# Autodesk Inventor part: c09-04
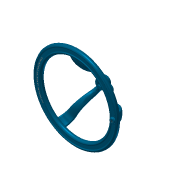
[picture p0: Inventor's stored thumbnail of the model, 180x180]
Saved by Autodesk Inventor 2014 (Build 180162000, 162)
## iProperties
Created: 2010-12
Part Number: c09-04
Document SubType Name: Modeling
Designer: Thom Tremblay
Density: 1 g/cm^3
Material: Generic
Appearance: Sky Blue Dark
Author: Thom Tremblay
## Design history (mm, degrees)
sketch "Sketch2"
  geometry: L1 (0, 0)-(-11.43, 0); L2 (-11.43, 0)-(-11.43, 16.51); L3 (-11.43, 16.51)-(0, 16.51); L4 (0, 16.51)-(0, 0); L5 (-96.52, 66.04)-(-86.36, 66.04); L6 (-86.36, 76.2)-(-96.52, 76.2); L7 (-95.25, 74.93)-(-87.63, 74.93); L8 (-96.52, 76.2)-(-95.25, 74.93); L9 (-86.36, 76.2)-(-87.63, 74.93); A1 r 5.08 centre (-86.36, 71.12) between (-86.36, 66.04) and (-86.36, 76.2); A2 r 5.08 centre (-96.52, 71.12) between (-96.52, 76.2) and (-96.52, 66.04)
  constraints: 18 end point, 4 parallel, 4 point on circle, 4 tangent, 2 centre point, 2 horizontal, 2 perpendicular
  dimensions: "d6" = 16.51 distance of L1.end L2.end; "d7" = 22.86 diameter of L2 L4; "d10" = 5.08 radius of A1; "d11" = 20.32 dimension on A2 A1; "d12" = 3.81 distance from line of A1.centre L7; "d13" = 7.62 distance of L7.start L7.end; "d14" = 76.2 distance from line of L6.end L1; "d15" = 203.2 dimension on A2 L4
revolve "Revolution1" sketch "Sketch2" stored, may be unused: angle "d16" = 120 deg
sketch "Sketch3"
  geometry: L1 (-91.007, -8.89)-(-91.007, 8.89); A1 r 88.9 centre (0, 0) between (-88.479, 8.643) and (-88.479, -8.643); A2 r 93.98 centre (0, 0) between (-93.535, 9.137) and (-93.535, -9.137); A3 r 2.54 centre (-91.007, -8.89) between (-88.479, -8.643) and (-93.535, -9.137); A4 r 2.54 centre (-91.007, 8.89) between (-88.479, 8.643) and (-93.535, 9.137); 2 further points
  constraints: 8 point on circle, 4 centre point, 4 tangent, 2 end point, 1 coincident, 1 midpoint, 1 vertical
  dimensions: "d17" = 17.78 distance of L1.start L1.end; "d18" = 88.9 radius of A1; "d19" = 5.08 diameter of A4
workplane "Work Plane1"
sketch "Sketch4"
  geometry: C1 r 5.08 at (0, 0.635); 1 further point
  constraints: 1 centre point
  dimensions: "d20" = 10.16 diameter of C1; "d21" = 8.89 distance of C1.centre point (0, -8.255)
sketch "3D Sketch1"
sketch "Sketch5"
  geometry: L1 (-91.007, 66.04)-(-91.007, 79.034); L2 (-11.43, 8.89)-(3.26, 8.89); A1 r 19.955 centre (-11.43, 28.845) between (-29.248, 19.86) and (-11.43, 8.89); A2 r 45.954 centre (-70.28, -0.83) between (-29.248, 19.86) and (-70.149, 45.123); A3 r 20.917 centre (-70.09, 66.04) between (-91.007, 66.04) and (-70.149, 45.123); 1 further point
  constraints: 6 point on circle, 4 end point, 4 tangent, 3 centre point, 1 perpendicular, 1 vertical
loft "Loft1" sketch "3D Sketch1", "Sketch5" dims "d22" = 0, "d23" = 90 deg, "d24" = 0, "d25" = 90 deg, "d26" = 0, "d27" = 90 deg
fillet "Fillet1" dims "d28" = 2.54
pattern_circular "Circular Pattern1" dims "d30" = 360 deg
sketch "Sketch6"
  geometry: L1 (-5.08, 3.556)-(5.08, 3.556); L2 (5.08, 3.556)-(5.08, -3.556); L3 (5.08, -3.556)-(-5.08, -3.556); L4 (-5.08, -3.556)-(-5.08, 3.556); 3 further points
  constraints: 8 end point, 2 midpoint, 2 parallel, 1 horizontal, 1 horizontal alignment, 1 perpendicular, 1 vertical alignment
  dimensions: "d32" = 7.112 distance of L3.end L1.start; "d33" = 10.16 distance of L1.start L1.end
extrude "Extrusion2" cut sketch "Sketch6" stored distance "d34" = 25.4; taper "d35" = 0 deg
fillet "Fillet2" dims "d36" = 1.27
sketch "Sketch7"
  geometry: C1 r 6.35 at (91.44, 0); 1 further point
  constraints: 1 centre point
  dimensions: "d37" = 12.7 diameter of C1; "d38" = 91.44 distance of point (0, 0) C1.centre
extrude "Extrusion3" join sketch "Sketch7" distance "d39" = 3.81; taper "d40" = -2 deg
fillet "Fillet3" dims "d41" = 1.27
hole "Hole1" diameter "d44" = 4.9784; stored, may be unused: countersink angle "d48" = 82 deg, drill point angle "d50" = 118 deg; dims "d42" = 25.4, "d43" = 25.4, "d45" = 10.16, "d46" = 9.525, "d47" = 6.35, "d49" = 12.7
sketch "Sketch8"
  geometry: L1 (0, 0)-(-77.65, -44.831); L2 (0, 0)-(-89.662, 0); L3 (0, 0)-(-77.65, 44.831); A1 r 89.662 centre (0, 0) between (-77.65, 44.831) and (-76.203, -47.249); 1 further point
  constraints: 6 end point, 4 point on circle, 1 centre point, 1 coincident, 1 horizontal, 1 other
  dimensions: "d51" = 89.662 radius of A1; "d52" = 30 deg angle of L2 L3 (= 0.5 x d53); "d53" = 60 deg angle of L1 L3
emboss "Emboss1" sketch "Sketch8" dims "d56" = 0.762, "d57" = 0
fillet "Fillet4" dims "d58" = 1.27
body "Solid1"
node "3D Intersection1"
